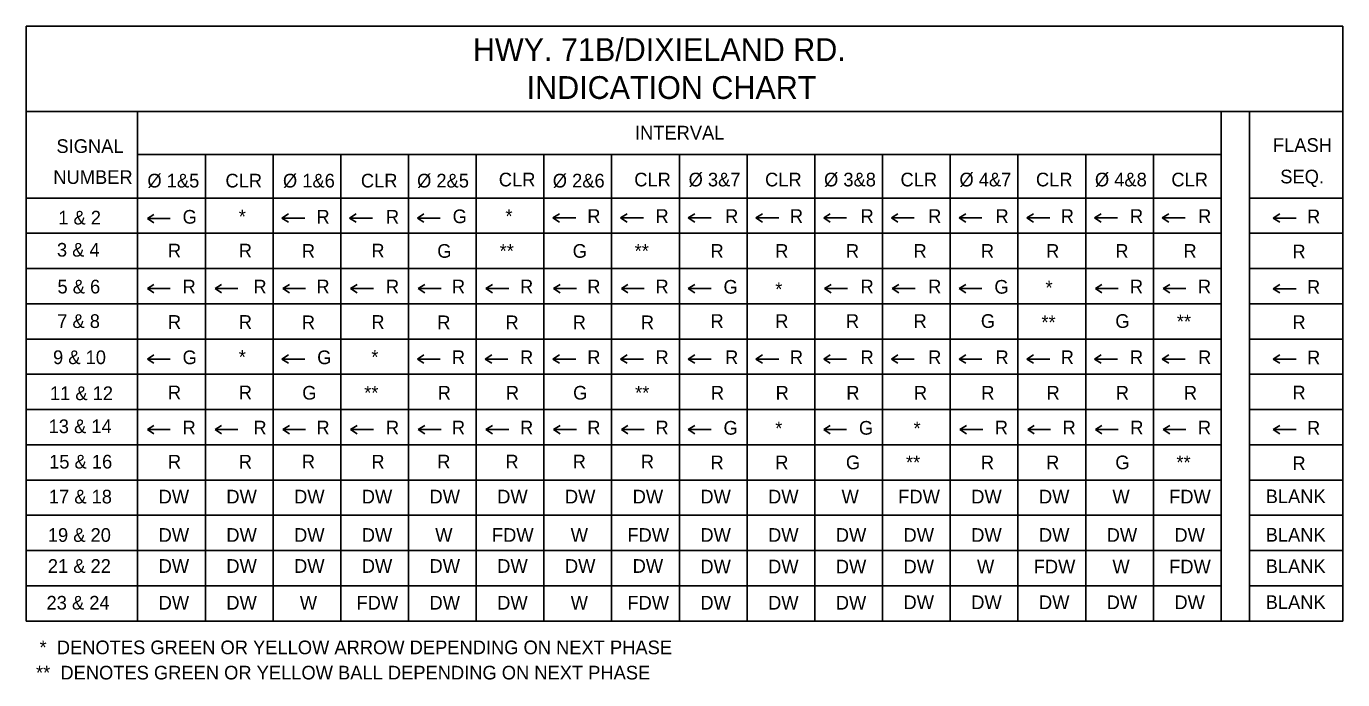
# Model space of a CAD drawing. Extents: x -15.7 to 19.3, y -1.4 to 10.8.
# Drawn here: x -8.04 to -0.35, y -0.85 to 2.97 of the extents above; entities that cross this region are included whole.
import ezdxf

# ---------------------------------------------------------------- set-up
doc = ezdxf.new("R2010")
doc.units = 0
for name, color, linetype in [('$', 7, 'Continuous'), ('PHASE', 7, 'Continuous'), ('TBLBDR', 7, 'Continuous'), ('TBLLINE', 7, 'Continuous'), ('TBLTEXT', 7, 'Continuous'), ('TITEXT', 7, 'Continuous')]:
    doc.layers.add(name, color=color, linetype=linetype)

msp = doc.modelspace()

# ---------------------------------------------------------------- linework, layer by layer
at = {"layer": 'PHASE'}
for p, q in [((-7.3347, 1.8504), (-7.2963, 1.8747)), ((-7.3347, 1.8504), (-7.2963, 1.8262)), ((-7.2011, 1.8504), (-7.3347, 1.8504)), ((-6.5479, 1.8533), (-6.5095, 1.8776)), ((-6.5479, 1.8533), (-6.5095, 1.829)), ((-6.4143, 1.8533), (-6.5479, 1.8533)), ((-6.1521, 1.8533), (-6.1136, 1.8776)), ((-6.1521, 1.8533), (-6.1136, 1.829)), ((-6.0185, 1.8533), (-6.1521, 1.8533)), ((-5.7563, 1.8533), (-5.7178, 1.8776)), ((-5.7563, 1.8533), (-5.7178, 1.829)), ((-5.6226, 1.8533), (-5.7563, 1.8533)), ((-4.9646, 1.8541), (-4.9261, 1.8784)), ((-4.9646, 1.8541), (-4.9261, 1.8298)), ((-4.8309, 1.8541), (-4.9646, 1.8541)), ((-4.5687, 1.8541), (-4.5303, 1.8784)), ((-4.5687, 1.8541), (-4.5303, 1.8298)), ((-4.4351, 1.8541), (-4.5687, 1.8541)), ((-4.1729, 1.8541), (-4.1344, 1.8784)), ((-4.1729, 1.8541), (-4.1344, 1.8298)), ((-4.0393, 1.8541), (-4.1729, 1.8541)), ((-3.7771, 1.8541), (-3.7386, 1.8784)), ((-3.7771, 1.8541), (-3.7386, 1.8298)), ((-3.6434, 1.8541), (-3.7771, 1.8541)), ((-3.3812, 1.8541), (-3.3427, 1.8784)), ((-3.3812, 1.8541), (-3.3427, 1.8298)), ((-3.2476, 1.8541), (-3.3812, 1.8541)), ((-2.9854, 1.8541), (-2.9469, 1.8784)), ((-2.9854, 1.8541), (-2.9469, 1.8298)), ((-2.8517, 1.8541), (-2.9854, 1.8541)), ((-2.5895, 1.8541), (-2.5511, 1.8784)), ((-2.5895, 1.8541), (-2.5511, 1.8298)), ((-2.4559, 1.8541), (-2.5895, 1.8541)), ((-2.1937, 1.8541), (-2.1552, 1.8784)), ((-2.1937, 1.8541), (-2.1552, 1.8298)), ((-2.0601, 1.8541), (-2.1937, 1.8541)), ((-1.7979, 1.8541), (-1.7594, 1.8784)), ((-1.7979, 1.8541), (-1.7594, 1.8298)), ((-1.6642, 1.8541), (-1.7979, 1.8541)), ((-1.402, 1.8541), (-1.3635, 1.8784)), ((-1.402, 1.8541), (-1.3635, 1.8298)), ((-1.2684, 1.8541), (-1.402, 1.8541)), ((-0.7538, 1.8533), (-0.7153, 1.8776)), ((-0.7538, 1.8533), (-0.7153, 1.829)), ((-0.6202, 1.8533), (-0.7538, 1.8533)), ((-7.3347, 1.441), (-7.2963, 1.4653)), ((-6.9389, 1.441), (-6.9004, 1.4653)), ((-6.543, 1.441), (-6.5046, 1.4653)), ((-6.1472, 1.441), (-6.1087, 1.4653)), ((-5.7514, 1.441), (-5.7129, 1.4653)), ((-5.3555, 1.441), (-5.3171, 1.4653)), ((-4.9597, 1.441), (-4.9212, 1.4653)), ((-4.5639, 1.441), (-4.5254, 1.4653)), ((-4.1729, 1.441), (-4.1344, 1.4653)), ((-3.3763, 1.441), (-3.3379, 1.4653)), ((-2.9805, 1.441), (-2.942, 1.4653)), ((-2.5895, 1.441), (-2.5511, 1.4653)), ((-1.793, 1.441), (-1.7545, 1.4653)), ((-1.3971, 1.441), (-1.3587, 1.4653)), ((-0.7538, 1.4406), (-0.7153, 1.4649)), ((-7.3347, 1.441), (-7.2963, 1.4168)), ((-7.2011, 1.441), (-7.3347, 1.441)), ((-6.9389, 1.441), (-6.9004, 1.4168)), ((-6.8053, 1.441), (-6.9389, 1.441)), ((-6.543, 1.441), (-6.5046, 1.4168)), ((-6.4094, 1.441), (-6.543, 1.441)), ((-6.1472, 1.441), (-6.1087, 1.4168)), ((-6.0136, 1.441), (-6.1472, 1.441)), ((-5.7514, 1.441), (-5.7129, 1.4168)), ((-5.6177, 1.441), (-5.7514, 1.441)), ((-5.3555, 1.441), (-5.3171, 1.4168)), ((-5.2219, 1.441), (-5.3555, 1.441)), ((-4.9597, 1.441), (-4.9212, 1.4168)), ((-4.8261, 1.441), (-4.9597, 1.441)), ((-4.5639, 1.441), (-4.5254, 1.4168)), ((-4.4302, 1.441), (-4.5639, 1.441)), ((-4.1729, 1.441), (-4.1344, 1.4168)), ((-4.0393, 1.441), (-4.1729, 1.441)), ((-3.3763, 1.441), (-3.3379, 1.4168)), ((-3.2427, 1.441), (-3.3763, 1.441)), ((-2.9805, 1.441), (-2.942, 1.4168)), ((-2.8469, 1.441), (-2.9805, 1.441)), ((-2.5895, 1.441), (-2.5511, 1.4168)), ((-2.4559, 1.441), (-2.5895, 1.441)), ((-1.793, 1.441), (-1.7545, 1.4168)), ((-1.6593, 1.441), (-1.793, 1.441)), ((-1.3971, 1.441), (-1.3587, 1.4168)), ((-1.2635, 1.441), (-1.3971, 1.441)), ((-0.7538, 1.4406), (-0.7153, 1.4164)), ((-0.6202, 1.4406), (-0.7538, 1.4406)), ((-7.3347, 1.0288), (-7.2963, 1.053)), ((-7.3347, 1.0288), (-7.2963, 1.0045)), ((-7.2011, 1.0288), (-7.3347, 1.0288)), ((-6.5479, 1.0288), (-6.5095, 1.053)), ((-6.5479, 1.0288), (-6.5095, 1.0045)), ((-6.4143, 1.0288), (-6.5479, 1.0288)), ((-5.7563, 1.0288), (-5.7178, 1.053)), ((-5.7563, 1.0288), (-5.7178, 1.0045)), ((-5.6226, 1.0288), (-5.7563, 1.0288)), ((-5.3604, 1.0288), (-5.3219, 1.053)), ((-5.3604, 1.0288), (-5.3219, 1.0045)), ((-5.2268, 1.0288), (-5.3604, 1.0288)), ((-4.9646, 1.0288), (-4.9261, 1.053)), ((-4.9646, 1.0288), (-4.9261, 1.0045)), ((-4.8309, 1.0288), (-4.9646, 1.0288)), ((-4.5687, 1.0288), (-4.5303, 1.053)), ((-4.5687, 1.0288), (-4.5303, 1.0045)), ((-4.4351, 1.0288), (-4.5687, 1.0288)), ((-4.1729, 1.0288), (-4.1344, 1.053)), ((-4.1729, 1.0288), (-4.1344, 1.0045)), ((-4.0393, 1.0288), (-4.1729, 1.0288)), ((-3.7771, 1.0288), (-3.7386, 1.053)), ((-3.7771, 1.0288), (-3.7386, 1.0045)), ((-3.6434, 1.0288), (-3.7771, 1.0288)), ((-3.3812, 1.0288), (-3.3427, 1.053)), ((-3.3812, 1.0288), (-3.3427, 1.0045)), ((-3.2476, 1.0288), (-3.3812, 1.0288)), ((-2.9854, 1.0288), (-2.9469, 1.053)), ((-2.9854, 1.0288), (-2.9469, 1.0045)), ((-2.8517, 1.0288), (-2.9854, 1.0288)), ((-2.5895, 1.0288), (-2.5511, 1.053)), ((-2.5895, 1.0288), (-2.5511, 1.0045)), ((-2.4559, 1.0288), (-2.5895, 1.0288)), ((-2.1937, 1.0288), (-2.1552, 1.053)), ((-2.1937, 1.0288), (-2.1552, 1.0045)), ((-2.0601, 1.0288), (-2.1937, 1.0288)), ((-1.7979, 1.0288), (-1.7594, 1.053)), ((-1.7979, 1.0288), (-1.7594, 1.0045)), ((-1.6642, 1.0288), (-1.7979, 1.0288)), ((-1.402, 1.0288), (-1.3635, 1.053)), ((-1.402, 1.0288), (-1.3635, 1.0045)), ((-1.2684, 1.0288), (-1.402, 1.0288)), ((-0.7538, 1.0288), (-0.7153, 1.053)), ((-0.7538, 1.0288), (-0.7153, 1.0045)), ((-0.6202, 1.0288), (-0.7538, 1.0288)), ((-7.3347, 0.6165), (-7.2963, 0.6408)), ((-7.3347, 0.6165), (-7.2963, 0.5922)), ((-7.2011, 0.6165), (-7.3347, 0.6165)), ((-6.9389, 0.6165), (-6.9004, 0.6408)), ((-6.9389, 0.6165), (-6.9004, 0.5922)), ((-6.8053, 0.6165), (-6.9389, 0.6165)), ((-6.543, 0.6165), (-6.5046, 0.6408)), ((-6.543, 0.6165), (-6.5046, 0.5922)), ((-6.4094, 0.6165), (-6.543, 0.6165)), ((-6.1472, 0.6165), (-6.1087, 0.6408)), ((-6.1472, 0.6165), (-6.1087, 0.5922)), ((-6.0136, 0.6165), (-6.1472, 0.6165)), ((-5.7514, 0.6165), (-5.7129, 0.6408)), ((-5.7514, 0.6165), (-5.7129, 0.5922)), ((-5.6177, 0.6165), (-5.7514, 0.6165)), ((-5.3555, 0.6165), (-5.3171, 0.6408)), ((-5.3555, 0.6165), (-5.3171, 0.5922)), ((-5.2219, 0.6165), (-5.3555, 0.6165)), ((-4.9597, 0.6165), (-4.9212, 0.6408)), ((-4.9597, 0.6165), (-4.9212, 0.5922)), ((-4.8261, 0.6165), (-4.9597, 0.6165)), ((-4.5639, 0.6165), (-4.5254, 0.6408)), ((-4.5639, 0.6165), (-4.5254, 0.5922)), ((-4.4302, 0.6165), (-4.5639, 0.6165)), ((-4.1729, 0.6165), (-4.1344, 0.6408)), ((-4.1729, 0.6165), (-4.1344, 0.5922)), ((-4.0393, 0.6165), (-4.1729, 0.6165)), ((-3.3812, 0.6165), (-3.3427, 0.6408)), ((-3.3812, 0.6165), (-3.3427, 0.5922)), ((-3.2476, 0.6165), (-3.3812, 0.6165)), ((-2.5847, 0.6165), (-2.5462, 0.6408)), ((-2.5847, 0.6165), (-2.5462, 0.5922)), ((-2.451, 0.6165), (-2.5847, 0.6165)), ((-2.1888, 0.6165), (-2.1503, 0.6408)), ((-2.1888, 0.6165), (-2.1503, 0.5922)), ((-2.0552, 0.6165), (-2.1888, 0.6165)), ((-1.793, 0.6165), (-1.7545, 0.6408)), ((-1.793, 0.6165), (-1.7545, 0.5922)), ((-1.6593, 0.6165), (-1.793, 0.6165)), ((-1.3971, 0.6165), (-1.3587, 0.6408)), ((-1.3971, 0.6165), (-1.3587, 0.5922)), ((-1.2635, 0.6165), (-1.3971, 0.6165)), ((-0.7538, 0.6169), (-0.7153, 0.6412)), ((-0.7538, 0.6169), (-0.7153, 0.5926)), ((-0.6202, 0.6169), (-0.7538, 0.6169))]:
    msp.add_line(p, q, dxfattribs=at)
at = {"layer": 'TBLBDR'}
for p, q in [((-8.0421, 2.4771), (-8.0421, -0.5028)), ((-8.0421, 2.4771), (-0.3475, 2.4771)), ((-7.3916, -0.5028), (-7.3916, 2.4771)), ((-1.0581, -0.5028), (-1.0581, 2.4771)), ((-0.8918, 2.4771), (-0.8918, -0.5028)), ((-0.3475, -0.5028), (-0.3475, 2.4771)), ((-4.2248, -0.5028), (-4.2248, 2.2244)), ((-8.0421, 1.9709), (-1.0581, 1.9709)), ((-0.8918, 1.9709), (-0.3475, 1.9709))]:
    msp.add_line(p, q, dxfattribs=at)
msp.add_lwpolyline([(-8.0421, 2.9749), (-0.3475, 2.9749), (-0.3475, 2.4771), (-8.0421, 2.4771)], close=True, dxfattribs=at)
at = {"layer": 'TBLLINE'}
for p, q in [((-7.3916, 2.2244), (-1.0581, 2.2244)), ((-6.9957, -0.5028), (-6.9957, 2.2244)), ((-6.5999, -0.5028), (-6.5999, 2.2244)), ((-6.204, -0.5028), (-6.204, 2.2244)), ((-5.8082, -0.5028), (-5.8082, 2.2244)), ((-5.4124, -0.5028), (-5.4124, 2.2244)), ((-5.0165, -0.5028), (-5.0165, 2.2244)), ((-4.6207, -0.5028), (-4.6207, 2.2244)), ((-3.829, -0.5028), (-3.829, 2.2244)), ((-3.4332, -0.5028), (-3.4332, 2.2244)), ((-3.0373, -0.5028), (-3.0373, 2.2244)), ((-2.6415, -0.5028), (-2.6415, 2.2244)), ((-2.2456, -0.5028), (-2.2456, 2.2244)), ((-1.8498, -0.5028), (-1.8498, 2.2244)), ((-1.454, -0.5028), (-1.454, 2.2244)), ((-8.0421, 1.7647), (-1.0581, 1.7647)), ((-0.8918, 1.7655), (-0.3475, 1.7655)), ((-8.0421, 1.5586), (-1.0581, 1.5586)), ((-0.8918, 1.559), (-0.3475, 1.559)), ((-8.0421, 1.3525), (-1.0581, 1.3525)), ((-0.8918, 1.3525), (-0.3475, 1.3525)), ((-8.0421, 1.1463), (-1.0581, 1.1463)), ((-0.8918, 1.1459), (-0.3475, 1.1459)), ((-8.0421, 0.9402), (-1.0581, 0.9402)), ((-0.8918, 0.9406), (-0.3475, 0.9406)), ((-8.0421, 0.734), (-1.0581, 0.734)), ((-0.8918, 0.734), (-0.3475, 0.734)), ((-8.0421, 0.5279), (-1.0581, 0.5279)), ((-0.8918, 0.5275), (-0.3475, 0.5275)), ((-8.0421, 0.3218), (-1.0581, 0.3218)), ((-0.8918, 0.321), (-0.3475, 0.321)), ((-8.0421, 0.1156), (-1.0581, 0.1156)), ((-0.8918, 0.1156), (-0.3475, 0.1156)), ((-8.0421, -0.0905), (-1.0581, -0.0905)), ((-0.8918, -0.0909), (-0.3475, -0.0909)), ((-8.0421, -0.2967), (-1.0581, -0.2967)), ((-0.8918, -0.2975), (-0.3475, -0.2975)), ((-8.0421, -0.5028), (-0.3475, -0.5028))]:
    msp.add_line(p, q, dxfattribs=at)

# ---------------------------------------------------------------- texts
at = {"layer": '$'}
for s, p in [('HWY. 71B/DIXIELAND RD.', (-5.4318, 2.7722)), ('INDICATION CHART', (-5.1175, 2.5502))]:
    msp.add_text(s, height=0.133334, dxfattribs=at).set_placement(p)
at = {"layer": 'TBLTEXT'}
for s, p in [('1 & 2', (-7.8555, 1.816)), ('G', (-7.1287, 1.8209)), ('*', (-6.8003, 1.8225)), ('R', (-6.3464, 1.8215)), ('R', (-5.94, 1.8209)), ('G', (-5.5502, 1.8238)), ('*', (-5.2416, 1.8246)), ('R', (-4.763, 1.8255)), ('R', (-4.3646, 1.8255)), ('R', (-3.9576, 1.8251)), ('R', (-3.5791, 1.8251)), ('R', (-3.166, 1.8251)), ('R', (-2.7707, 1.8251)), ('R', (-2.3771, 1.8251)), ('R', (-1.9958, 1.8251)), ('R', (-1.591, 1.8251)), ('R', (-1.1929, 1.8251)), ('R', (-0.5559, 1.8234)), ('3 & 4', (-7.8631, 1.6283)), ('R', (-7.2145, 1.6233)), ('R', (-6.8003, 1.6233)), ('R', (-6.4317, 1.6213)), ('R', (-6.0254, 1.6233)), ('G', (-5.6401, 1.6213)), ('**', (-5.2753, 1.6213)), ('G', (-4.8484, 1.6213)), ('**', (-4.4861, 1.6213)), ('R', (-4.043, 1.6213)), ('R', (-3.6645, 1.6213)), ('R', (-3.2513, 1.6213)), ('R', (-2.8561, 1.6213)), ('R', (-2.4625, 1.6213)), ('R', (-2.0811, 1.6213)), ('R', (-1.6764, 1.6213)), ('R', (-1.2783, 1.6213)), ('R', (-0.6413, 1.6181)), ('5 & 6', (-7.8601, 1.4128)), ('R', (-7.1291, 1.4128)), ('R', (-6.7149, 1.4128)), ('R', (-6.3464, 1.4134)), ('R', (-5.94, 1.4128)), ('R', (-5.5547, 1.4134)), ('R', (-5.1563, 1.4134)), ('R', (-4.763, 1.4134)), ('R', (-4.3646, 1.4134)), ('G', (-3.9668, 1.4115)), ('*', (-3.6645, 1.3975)), ('R', (-3.166, 1.4134)), ('R', (-2.7707, 1.4134)), ('G', (-2.3835, 1.4115)), ('*', (-2.0847, 1.4067)), ('R', (-1.5916, 1.4134)), ('R', (-1.1936, 1.4134)), ('R', (-0.5559, 1.4107)), ('7 & 8', (-7.8616, 1.2109)), ('R', (-7.2145, 1.2059)), ('R', (-6.8003, 1.2059)), ('R', (-6.4317, 1.2039)), ('R', (-6.0254, 1.2059)), ('R', (-5.6401, 1.2039)), ('R', (-5.2416, 1.2039)), ('R', (-4.8484, 1.2039)), ('R', (-4.45, 1.2039)), ('R', (-4.043, 1.2114)), ('R', (-3.6645, 1.2114)), ('R', (-3.2513, 1.2114)), ('R', (-2.8561, 1.2114)), ('G', (-2.4625, 1.2114)), ('**', (-2.1086, 1.2039)), ('G', (-1.6764, 1.2114)), ('**', (-1.3169, 1.2089)), ('R', (-0.6413, 1.205)), ('9 & 10', (-7.886, 0.9997)), ('G', (-7.1287, 0.9993)), ('*', (-6.8003, 1.0012)), ('G', (-6.3419, 0.9993)), ('*', (-6.0254, 1.0012)), ('R', (-5.5547, 0.9998)), ('R', (-5.1563, 0.9998)), ('R', (-4.763, 1.0002)), ('R', (-4.3646, 1.0002)), ('R', (-3.9576, 0.9998)), ('R', (-3.5791, 0.9998)), ('R', (-3.166, 0.9998)), ('R', (-2.7707, 0.9998)), ('R', (-2.3771, 0.9998)), ('R', (-1.9958, 0.9998)), ('R', (-1.591, 0.9998)), ('R', (-1.1929, 0.9998)), ('R', (-0.5559, 0.9989)), ('11 & 12', (-7.9043, 0.7891)), ('R', (-7.2145, 0.794)), ('R', (-6.8003, 0.794)), ('G', (-6.4293, 0.792)), ('**', (-6.067, 0.792)), ('R', (-5.6376, 0.792)), ('R', (-5.2392, 0.792)), ('G', (-4.8459, 0.792)), ('**', (-4.4837, 0.792)), ('R', (-4.0406, 0.792)), ('R', (-3.6621, 0.792)), ('R', (-3.2489, 0.792)), ('R', (-2.8536, 0.792)), ('R', (-2.46, 0.792)), ('R', (-2.0787, 0.792)), ('R', (-1.6739, 0.792)), ('R', (-1.2759, 0.792)), ('R', (-0.6413, 0.7931)), ('13 & 14', (-7.9119, 0.5959)), ('R', (-7.1291, 0.5883)), ('R', (-6.7149, 0.5883)), ('R', (-6.3464, 0.5888)), ('R', (-5.94, 0.5883)), ('R', (-5.5547, 0.5888)), ('R', (-5.1563, 0.5888)), ('R', (-4.763, 0.5888)), ('R', (-4.3646, 0.5888)), ('G', (-3.9668, 0.587)), ('*', (-3.6645, 0.584)), ('G', (-3.1751, 0.587)), ('*', (-2.8561, 0.584)), ('R', (-2.3811, 0.5888)), ('R', (-1.9853, 0.5888)), ('R', (-1.5894, 0.5888)), ('R', (-1.1936, 0.5888)), ('R', (-0.5559, 0.587)), ('15 & 16', (-7.9088, 0.3891)), ('R', (-7.2145, 0.3891)), ('R', (-6.8003, 0.3891)), ('R', (-6.4317, 0.3897)), ('R', (-6.0254, 0.3891)), ('R', (-5.6401, 0.3897)), ('R', (-5.2416, 0.3897)), ('R', (-4.8484, 0.3897)), ('R', (-4.45, 0.3897)), ('R', (-4.043, 0.3848)), ('R', (-3.6645, 0.3848)), ('G', (-3.2513, 0.3848)), ('**', (-2.9003, 0.3848)), ('R', (-2.4625, 0.3848)), ('R', (-2.0811, 0.3848)), ('G', (-1.6764, 0.3848)), ('**', (-1.3194, 0.3848)), ('R', (-0.6413, 0.38)), ('17 & 18', (-7.9104, 0.1849)), ('DW', (-7.2688, 0.1849)), ('DW', (-6.873, 0.1849)), ('DW', (-6.4771, 0.1849)), ('DW', (-6.0813, 0.1849)), ('DW', (-5.6854, 0.1849)), ('DW', (-5.2896, 0.1849)), ('DW', (-4.8938, 0.1849)), ('DW', (-4.4979, 0.1849)), ('DW', (-4.1021, 0.1849)), ('DW', (-3.7062, 0.1849)), ('W', (-3.2768, 0.1849)), ('FDW', (-2.9453, 0.1849)), ('DW', (-2.5187, 0.1849)), ('DW', (-2.1229, 0.1849)), ('W', (-1.6934, 0.1849)), ('FDW', (-1.362, 0.1849)), ('BLANK', (-0.7976, 0.1865)), ('19 & 20', (-7.9165, -0.0396)), ('DW', (-7.2688, -0.0396)), ('DW', (-6.873, -0.0396)), ('DW', (-6.4771, -0.0396)), ('DW', (-6.0813, -0.0396)), ('W', (-5.6518, -0.0396)), ('FDW', (-5.3204, -0.0396)), ('W', (-4.8601, -0.0396)), ('FDW', (-4.5287, -0.0396)), ('DW', (-4.1021, -0.0396)), ('DW', (-3.7062, -0.0396)), ('DW', (-3.3104, -0.0396)), ('DW', (-2.9146, -0.0396)), ('DW', (-2.5187, -0.0396)), ('DW', (-2.1229, -0.0396)), ('DW', (-1.727, -0.0396)), ('DW', (-1.3312, -0.0396)), ('BLANK', (-0.7976, -0.0384)), ('21 & 22', (-7.9165, -0.2209)), ('DW', (-7.2688, -0.2209)), ('DW', (-6.873, -0.2209)), ('DW', (-6.4771, -0.2209)), ('DW', (-6.0813, -0.2209)), ('DW', (-5.6854, -0.2209)), ('DW', (-5.2896, -0.2209)), ('DW', (-4.8938, -0.2209)), ('DW', (-4.4979, -0.2209)), ('DW', (-4.1021, -0.2242)), ('DW', (-3.7062, -0.2242)), ('DW', (-3.3104, -0.2242)), ('DW', (-2.9146, -0.2242)), ('W', (-2.4851, -0.2242)), ('FDW', (-2.1537, -0.2242)), ('W', (-1.6934, -0.2242)), ('FDW', (-1.362, -0.2242)), ('BLANK', (-0.7976, -0.2222)), ('23 & 24', (-7.9241, -0.4357)), ('DW', (-7.2688, -0.4357)), ('DW', (-6.873, -0.4357)), ('W', (-6.4435, -0.4357)), ('FDW', (-6.1121, -0.4357)), ('DW', (-5.6854, -0.4357)), ('DW', (-5.2896, -0.4357)), ('W', (-4.8601, -0.4357)), ('FDW', (-4.5287, -0.4357)), ('DW', (-4.1021, -0.4357)), ('DW', (-3.7062, -0.4357)), ('DW', (-3.3104, -0.4357)), ('DW', (-2.9146, -0.4331)), ('DW', (-2.5187, -0.4331)), ('DW', (-2.1229, -0.4331)), ('DW', (-1.727, -0.4331)), ('DW', (-1.3312, -0.4331)), ('BLANK', (-0.7976, -0.4323)), ('  *  DENOTES GREEN OR YELLOW ARROW DEPENDING ON NEXT PHASE', (-8.0245, -0.6968)), (' **  DENOTES GREEN OR YELLOW BALL DEPENDING ON NEXT PHASE', (-8.0153, -0.8445))]:
    msp.add_text(s, height=0.08, dxfattribs=at).set_placement(p)
at = {"layer": 'TITEXT'}
for s, p in [('INTERVAL', (-4.4845, 2.313)), ('SIGNAL', (-7.8661, 2.2344)), ('FLASH', (-0.7551, 2.2406)), ('NUMBER', (-7.8843, 2.0531)), ('%%C 1&5', (-7.3343, 2.0324)), ('CLR', (-6.8781, 2.0324)), ('%%C 1&6', (-6.5421, 2.0324)), ('CLR', (-6.0864, 2.0324)), ('%%C 2&5', (-5.758, 2.0324)), ('CLR', (-5.2803, 2.0388)), ('%%C 2&6', (-4.9648, 2.0324)), ('CLR', (-4.4886, 2.0388)), ('%%C 3&7', (-4.1709, 2.0388)), ('CLR', (-3.7239, 2.0388)), ('%%C 3&8', (-3.3792, 2.0388)), ('CLR', (-2.9322, 2.0388)), ('%%C 4&7', (-2.5875, 2.0388)), ('CLR', (-2.1405, 2.0388)), ('%%C 4&8', (-1.7958, 2.0388)), ('CLR', (-1.3488, 2.0388)), ('SEQ.', (-0.7124, 2.0565))]:
    msp.add_text(s, height=0.08, dxfattribs=at).set_placement(p)

doc.saveas('drawing.dxf')
